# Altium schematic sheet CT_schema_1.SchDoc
size 510 x 267 mm
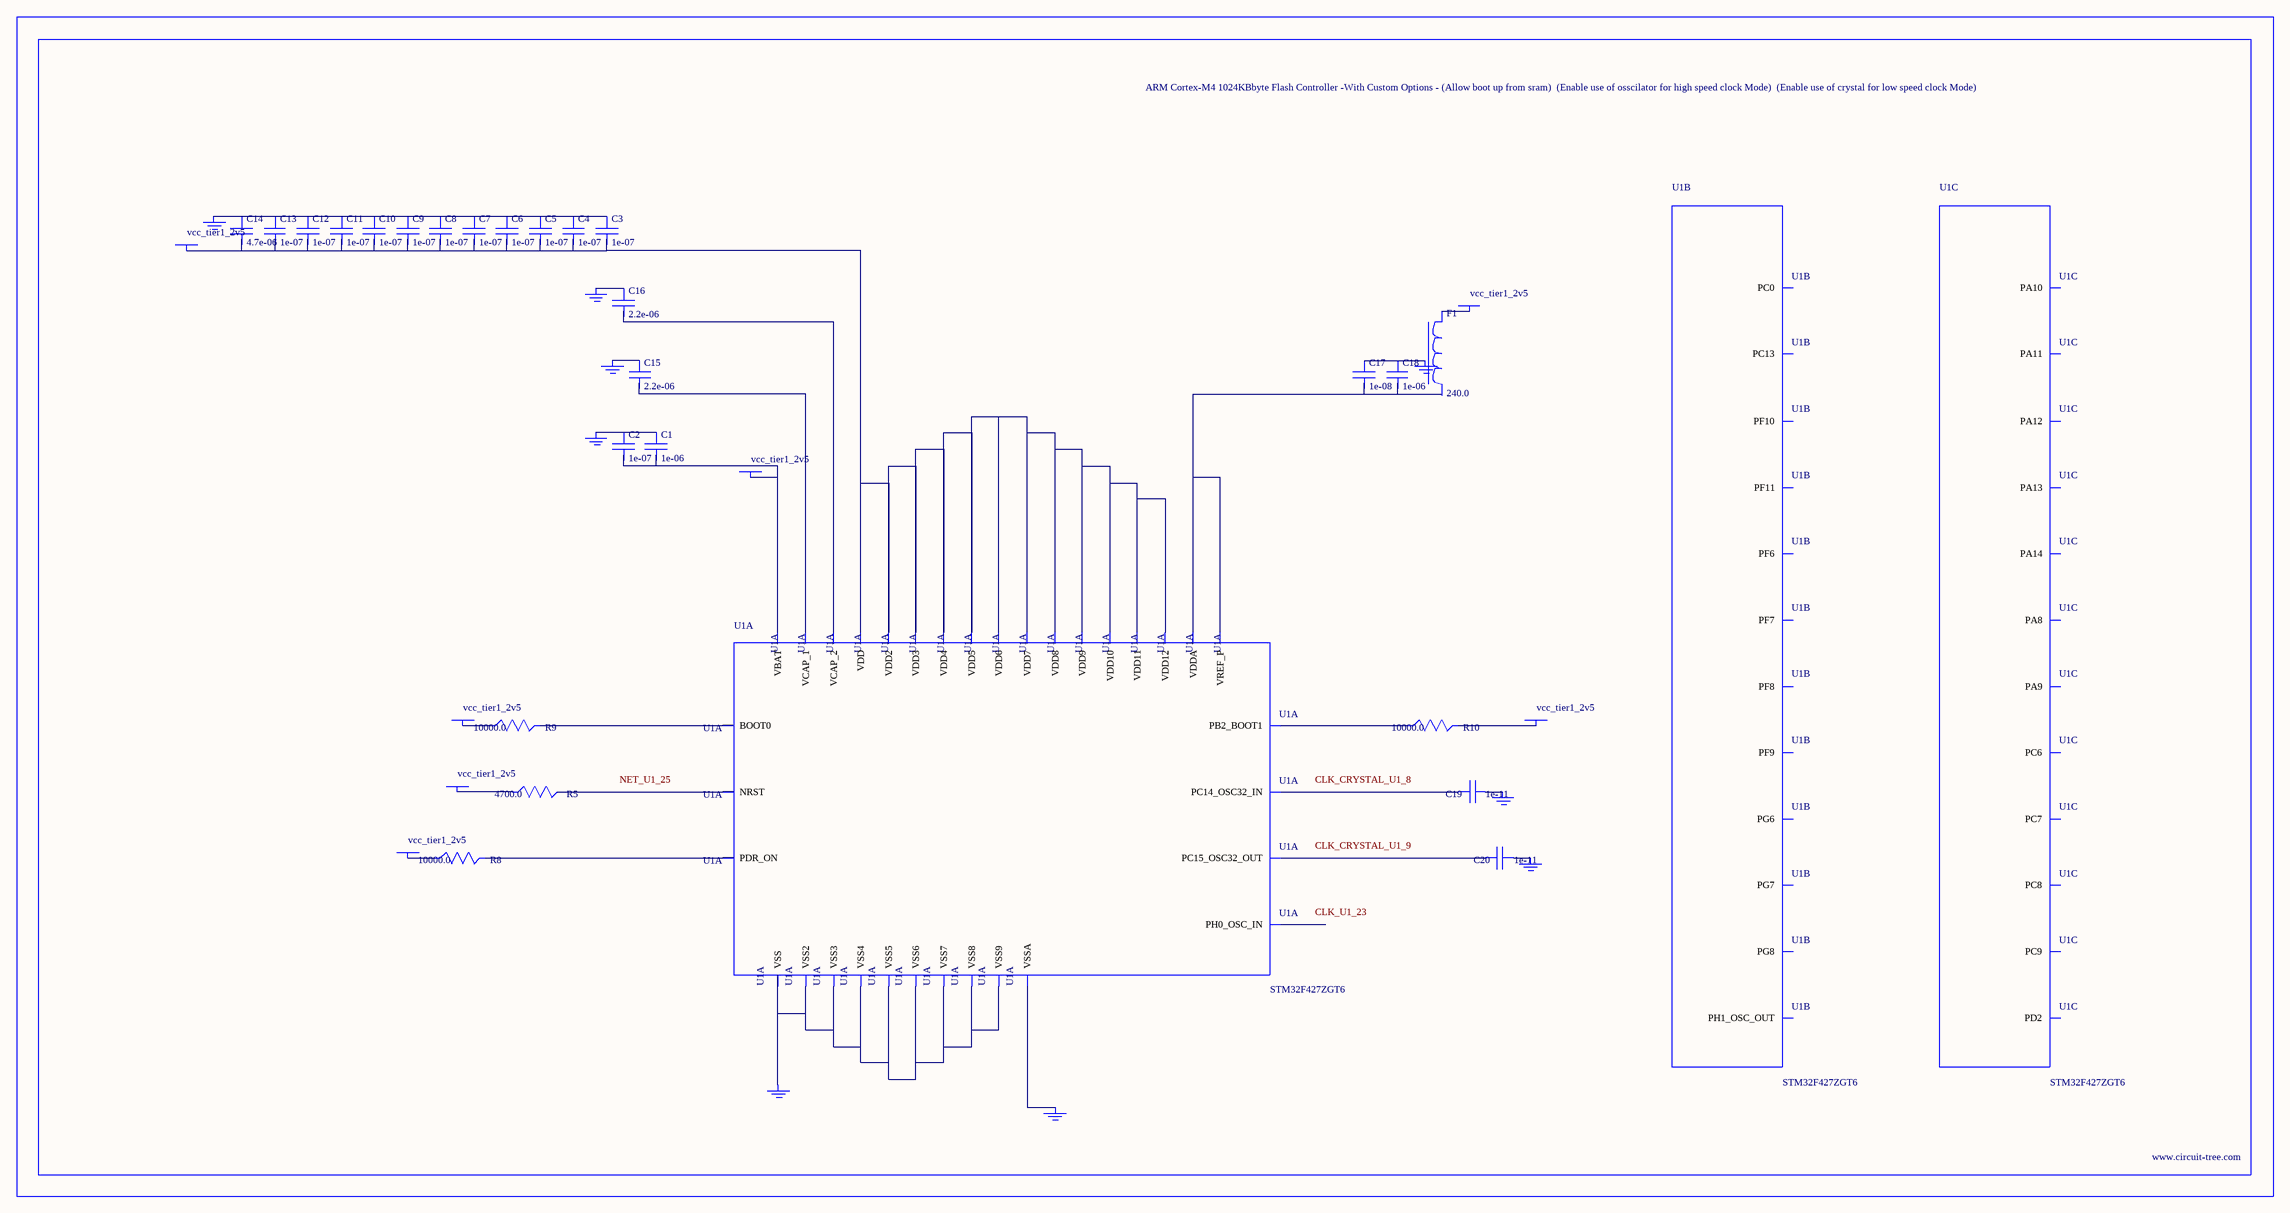
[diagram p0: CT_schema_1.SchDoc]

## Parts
BORDER0  (no value)
C1  1e-06  [C0603]
C2  1e-07  [C0603]
C3  1e-07  [C0603]
C4  1e-07  [C0603]
C5  1e-07  [C0603]
C6  1e-07  [C0603]
C7  1e-07  [C0603]
C8  1e-07  [C0603]
C9  1e-07  [C0603]
C10  1e-07  [C0603]
C11  1e-07  [C0603]
C12  1e-07  [C0603]
C13  1e-07  [C0603]
C14  4.7e-06  [C0603]
C15  2.2e-06  [C0603]
C16  2.2e-06  [C0603]
C17  1e-08  [C0603]
C18  1e-06  [C0603]
C19  1e-11  [C0402]
C20  1e-11  [C0402]
F1  240.0  [L0603]
GND_INSTANCE_0_0  (no value)
GND_INSTANCE_0_1  (no value)
GND_INSTANCE_0_2  (no value)
GND_INSTANCE_0_3  (no value)
GND_INSTANCE_0_4  (no value)
GND_INSTANCE_0_5  (no value)
GND_INSTANCE_0_6  (no value)
GND_INSTANCE_0_7  (no value)
GND_INSTANCE_0_8  (no value)
POWER_INSTANCE_0_0  vcc_tier1_2v5
POWER_INSTANCE_0_1  vcc_tier1_2v5
POWER_INSTANCE_0_2  vcc_tier1_2v5
POWER_INSTANCE_0_3  vcc_tier1_2v5
POWER_INSTANCE_0_4  vcc_tier1_2v5
POWER_INSTANCE_0_5  vcc_tier1_2v5
POWER_INSTANCE_0_6  vcc_tier1_2v5
R5  4700.0  [R0603]
R8  10000.0  [R0603]
R9  10000.0  [R0603]
R10  10000.0  [R0603]
U1  STM32F427ZGT6  [LQFP144]  (parts A,B,C of 12)

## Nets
NetC1_1: C1.1 C2.1 GND_INSTANCE_0_0.0(GND)
NetC1_2: C1.2 C2.2 POWER_INSTANCE_0_0.0(PWR) U1.6(VBAT)
NetC3_1: C3.1 C4.1 C5.1 C6.1 C7.1 C8.1 C9.1 C10.1 C11.1 C12.1 C13.1 C14.1 GND_INSTANCE_0_3.0(GND)
NetC3_2: C3.2 C4.2 C5.2 C6.2 C7.2 C8.2 C9.2 C10.2 C11.2 C12.2 C13.2 C14.2 POWER_INSTANCE_0_1.0(PWR) U1.17(VDD) U1.30(VDD2) U1.39(VDD3) U1.52(VDD4) U1.62(VDD5) U1.72(VDD6) U1.84(VDD7) U1.95(VDD8) U1.108(VDD9) U1.121(VDD10) U1.131(VDD11) U1.144(VDD12)
NetC15_1: C15.1 GND_INSTANCE_0_6.0(GND)
NetC15_2: C15.2 U1.71(VCAP_1)
NetC16_1: C16.1 GND_INSTANCE_0_7.0(GND)
NetC16_2: C16.2 U1.106(VCAP_2)
NetC17_1: C17.1 C18.1 GND_INSTANCE_0_5.0(GND)
NetC17_2: C17.2 C18.2 U1.32(VREF_P) U1.33(VDDA)
NetC19_1: C19.1 GND_INSTANCE_0_1.0(GND)
NetC19_2: C19.2 U1.8(PC14_OSC32_IN)
NetC20_1: C20.1 GND_INSTANCE_0_2.0(GND)
NetC20_2: C20.2 U1.9(PC15_OSC32_OUT)
NetF1_1: F1.1 POWER_INSTANCE_0_2.0(PWR)
NetGND_INSTANCE_0_4_0: GND_INSTANCE_0_4.0(GND) U1.31(VSSA)
NetGND_INSTANCE_0_8_0: GND_INSTANCE_0_8.0(GND) U1.16(VSS) U1.38(VSS2) U1.51(VSS3) U1.61(VSS4) U1.83(VSS5) U1.94(VSS6) U1.107(VSS7) U1.120(VSS8) U1.130(VSS9)
NetPOWER_INSTANCE_0_3_0: POWER_INSTANCE_0_3.0(PWR) R10.2
NetPOWER_INSTANCE_0_4_0: POWER_INSTANCE_0_4.0(PWR) R9.1
NetPOWER_INSTANCE_0_5_0: POWER_INSTANCE_0_5.0(PWR) R8.1
NetPOWER_INSTANCE_0_6_0: POWER_INSTANCE_0_6.0(PWR) R5.1
NetR5_2: R5.2 U1.25(NRST)
NetR8_2: R8.2 U1.143(PDR_ON)
NetR9_2: R9.2 U1.138(BOOT0)
NetR10_1: R10.1 U1.48(PB2_BOOT1)

Not connected (* = marked no-connect by the designer): F1 2; U1 7(PC13) 18(PF6) 19(PF7) 20(PF8) 21(PF9) 22(PF10) 23(PH0_OSC_IN) 24(PH1_OSC_OUT) 26(PC0) 49(PF11) 91(PG6) 92(PG7) 93(PG8) 96(PC6) 97(PC7) 98(PC8) 99(PC9) 100(PA8) 101(PA9) 102(PA10) 103(PA11) 104(PA12) 105(PA13) 109(PA14) 116(PD2)

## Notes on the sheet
- Labels drawn without touching a wire or pin: CLK_CRYSTAL_U1_8, CLK_CRYSTAL_U1_9, CLK_U1_23, NET_U1_25

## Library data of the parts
BORDER0 = BORDER_PAGE0
C1 C18 = C0603C105K3RACTU
C2-C13 = 06035C104K4Z2A
C14 = GRM188R6YA475KE15D
C15 C16 = C0603C225K8RACTU
C17 = 06035C103K4Z2A
C19 C20 = C0402C100K3GACTU
F1 = Z0603C241ASMST
GND_INSTANCE_0_0-GND_INSTANCE_0_8 = GND
POWER_INSTANCE_0_0-POWER_INSTANCE_0_6 = PWR
R5 = RC0603JR-074K7L
R8-R10 = RC0603JR-0710KL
